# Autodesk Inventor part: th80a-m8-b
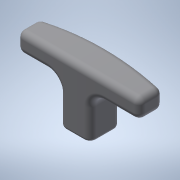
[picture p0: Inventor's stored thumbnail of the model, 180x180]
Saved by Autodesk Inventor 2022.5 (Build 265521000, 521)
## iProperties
Created: 2016-12
Part Number: th80a-m8-b
Material: 一般
Document SubType Name: Modeling
Designer: imaocorp
Density: 1 g/cm^3
Appearance: 既定
Author: imaocorp
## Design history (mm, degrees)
node "th80a-m8-b.x_t1"
node "th80a-m8-b"
node "Base1"
